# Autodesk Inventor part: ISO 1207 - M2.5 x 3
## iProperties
Comments: To add or edit properties for Autodesk Inventor files, use iProperties.
Created: 2004-07
Part Number: ISO 1207 - M2.5 x 3
Vendor: Autodesk Inc.
Document SubType Name: Modeling
Designer: John Blackburn
Material: Default
Description: Slotted Cheese Head Screw
Standard: ISO 1207
Size Designation: M2.5 x 3
Alert: To add or edit properties for Autodesk Inventor files, use iProperties.
Control State: 0
Master: False
Checked Out: False
Shininess: 64.0
Length Units: 11269
Angle Units: 11279
Time Units: 11290
Mass Units: 11283
Length Display Precision: 3
Angle Display Precision: 2
Compacted: True
EGR: 1
Classification: un/spsc 31161501
Density: 0.0
Volumn: 0.0
Area: 0.0
PropertySet Name: Model Information
Author: John Blackburn
Revision Number: 8
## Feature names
1. Body [Revolution]
2. Fillet1
3. Slot [Extrusion]
4. Chamfer1
